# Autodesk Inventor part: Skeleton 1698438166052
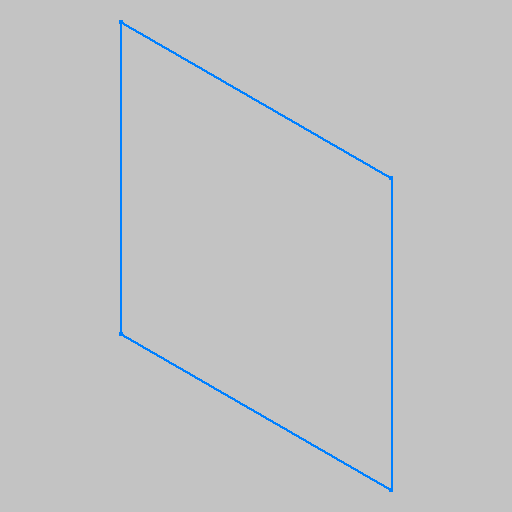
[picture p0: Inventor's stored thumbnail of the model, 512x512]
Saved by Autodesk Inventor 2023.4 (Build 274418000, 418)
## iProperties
Created: 2023-10
Part Number: Skeleton 1698438166052
Material: 10GA CRS
Document SubType Name: Sheet Metal
Designer: Fred L.
Density: 7.86 g/cm^3
Sheet Metal Rule: 10 ga
Appearance: Metal-Steel
Quantity: 0
Mass: 0
SurfaceArea: 0
_SkeletonDoc: Frame Skeleton File
_Version: 15.0.0
Author: Fred L.
Revision Number: 00
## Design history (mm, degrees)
sketch "Reference Skeleton"
body "Solid1"
other parameters: "Thickness" = 3.429 (derived), "KFactor" = 4.4, "BendRadius" = 3.429 (= Thickness), "BendReliefWidth" = 1.7145 (= 0.5 x Thickness), "BendReliefDepth" = 1.7145 (= 0.5 x Thickness), "CornerReliefSize" = 13.716 (= 4 x Thickness), "SeamGap" = 0.00508, "MinimumRemnant" = 6.858 (= 2 x Thickness), "TransitionRadius" = 3.429 (= BendRadius), "JacobiRadiusSize" = 3.429 (= BendRadius), "GapSize" = 0.254 (derived), "alga10" = 2.5908 [user parameter], "alga11" = 2.3114 [user parameter], "alga12" = 2.0574 [user parameter], "alga14" = 1.6256 [user parameter], "alga16" = 1.2954 [user parameter], "alga18" = 1.016 [user parameter], "alga20" = 0.8128 [user parameter], "alga22" = 0.635 [user parameter], "alga24" = 0.508 [user parameter], "ga9" = 3.6576 [user parameter], "ga10" = 3.4036 [user parameter], "ga11" = 3.0226 [user parameter], "ga12" = 2.65684 [user parameter], "ga14" = 1.89738 [user parameter], "ga16" = 1.51892 [user parameter], "ga18" = 1.21412 [user parameter], "ga20" = 0.91186 [user parameter], "ga22" = 0.75946 [user parameter], "ga24" = 0.60706 [user parameter], "gvga12" = 2.75336 [user parameter], "gvga14" = 1.9939 [user parameter], "gvga16" = 1.6129 [user parameter], "gvga18" = 1.31064 [user parameter], "gvga20" = 1.00584 [user parameter], "gvga22" = 0.85344 [user parameter], "gvga24" = 0.70104 [user parameter], "ssga10" = 3.57124 [user parameter], "ssga11" = 3.175 [user parameter], "ssga12" = 2.7686 [user parameter], "ssga14" = 1.98374 [user parameter], "ssga16" = 1.5875 [user parameter], "ssga18" = 1.27 [user parameter], "ssga20" = 0.9398 [user parameter], "ssga22" = 0.7874 [user parameter], "ssga24" = 0.635 [user parameter], "Length" = 0 [user parameter; used in 1 equation term], "Width" = 0 [user parameter; used in 1 equation term], "Area" = 0 (computed from Length, Width) [user parameter]
